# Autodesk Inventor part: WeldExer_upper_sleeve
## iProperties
Shininess: 64.0
Length Units: 11269
Angle Units: 11279
Time Units: 11290
Mass Units: 11286
Length Display Precision: 3
Angle Display Precision: 2
Compacted: True
Part Number: WeldExer_upper_sleeve
Document SubType Name: Modeling
Created: 2003-07
Designer: Ronald Myers
Manufacturer: Standard
Standards Organization: Custom
Stock Number: WeldExer_upper_sleeve
Density: 1 g/cm^3
Density: 0.0
Volumn: 0.0
Area: 0.0
PropertySet Name: Model Information
Control State: 0
Master: False
Checked Out: False
Author: Ronald Myers
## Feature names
1. Extrusion1
